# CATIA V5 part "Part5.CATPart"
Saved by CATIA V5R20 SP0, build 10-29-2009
Part number: 1DIN7991416_DIN 7991 - M4 x 16 --- 16C
Revision: ANY
Definition: UNKNOWN
Nomenclature: 1DIN7991416_DIN 7991 - M4 x 16 --- 16C
Source: Unknown
Bounding box of the stored display mesh (mm): x 0 to 16, y -3.633 to 3.633, z -3.82 to 3.82
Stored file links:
  C:\Users\Utente\Desktop\IO LAVORO\3D X SITO CF\CUMSA\3D files PW\pw060822\pw060822_injection\Part5.CATPart
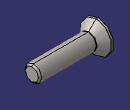
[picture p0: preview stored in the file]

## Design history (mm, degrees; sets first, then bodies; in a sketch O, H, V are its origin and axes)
Body1 "Hex" (main body)
  Solid1: solid without history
